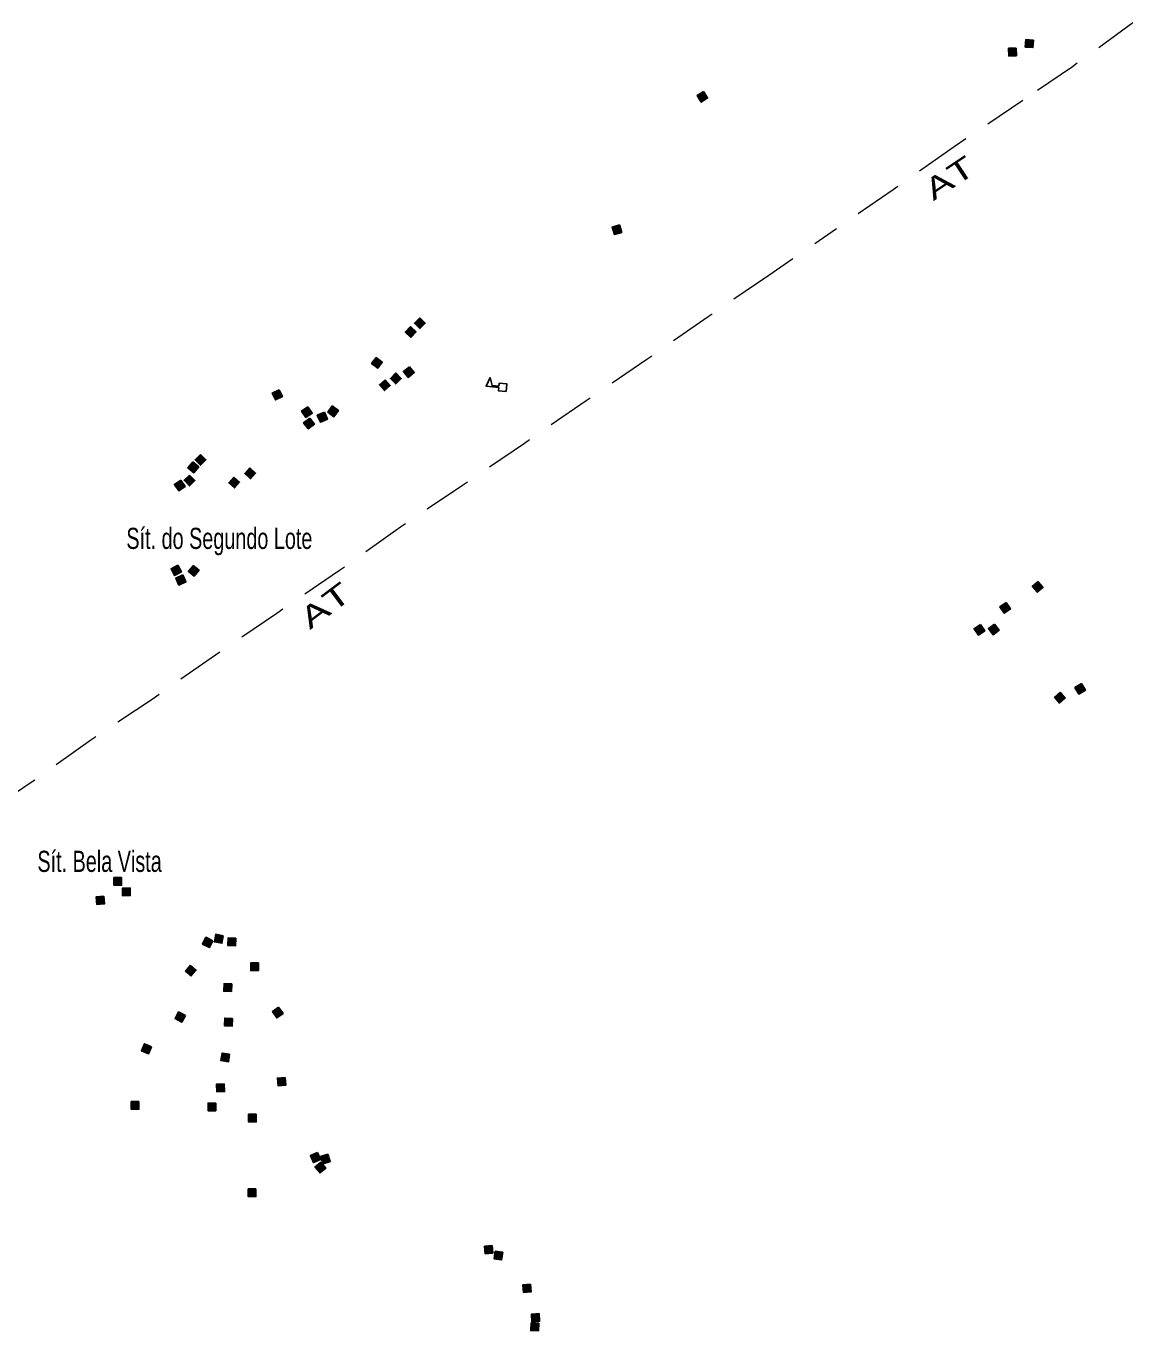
# Model space of a CAD drawing. Extents: x 679 to 705, y 7427.4 to 7455.4.
# Drawn here: x 687.983 to 692.169, y 7435.063 to 7439.999 of the extents above; entities that cross this region are included whole.
import ezdxf
from ezdxf.enums import TextEntityAlignment as Align

# ---------------------------------------------------------------- set-up
doc = ezdxf.new("R2010")
doc.units = 0
doc.header["$LTSCALE"] = 0.032
doc.linetypes.add('DOT_DASHED', pattern=[7.7, 5, -1.2, 0.3, -1.2])
for name, color, linetype, lineweight in [('2', 7, 'Continuous', 25), ('4', 7, 'Continuous', 25), ('56', 7, 'DOT_DASHED', 13)]:
    doc.layers.add(name, color=color, linetype=linetype, lineweight=lineweight)
doc.layers.add('61', color=7, linetype='Continuous')

msp = doc.modelspace()

# ---------------------------------------------------------------- hatches: boundary and pattern name
at = {"layer": '2'}
for points in [[(691.7282, 7439.9161), (691.7291, 7439.8871), (691.7001, 7439.8863), (691.6993, 7439.9152)], [(691.7935, 7439.9465), (691.7912, 7439.9176), (691.7623, 7439.9199), (691.7646, 7439.9488)], [(690.5453, 7439.7517), (690.5609, 7439.7272), (690.5365, 7439.7116), (690.5209, 7439.7361)], [(690.2281, 7439.2468), (690.2361, 7439.2189), (690.2082, 7439.2109), (690.2002, 7439.2387)], [(689.4724, 7438.8958), (689.4931, 7438.8755), (689.4728, 7438.8548), (689.4521, 7438.8751)], [(689.4369, 7438.8623), (689.458, 7438.8425), (689.4382, 7438.8213), (689.417, 7438.8412)], [(689.3071, 7438.7456), (689.3304, 7438.7283), (689.3131, 7438.705), (689.2898, 7438.7223)], [(689.3819, 7438.6868), (689.4022, 7438.6661), (689.3815, 7438.6458), (689.3612, 7438.6665)], [(689.4332, 7438.7107), (689.4514, 7438.6881), (689.4288, 7438.6699), (689.4106, 7438.6925)], [(689.3417, 7438.6613), (689.3606, 7438.6393), (689.3386, 7438.6204), (689.3197, 7438.6423)], [(688.9398, 7438.6237), (688.9528, 7438.5978), (688.9268, 7438.5848), (688.9139, 7438.6107)], [(689.049, 7438.5589), (689.0652, 7438.5348), (689.0411, 7438.5186), (689.0249, 7438.5427)], [(689.1113, 7438.5388), (689.123, 7438.5123), (689.0965, 7438.5006), (689.0847, 7438.5271)], [(689.1413, 7438.5621), (689.1646, 7438.5449), (689.1473, 7438.5216), (689.124, 7438.5388)], [(689.056, 7438.516), (689.0734, 7438.4928), (689.0502, 7438.4754), (689.0328, 7438.4986)], [(688.6138, 7438.3502), (688.6361, 7438.3317), (688.6175, 7438.3094), (688.5952, 7438.328)], [(688.6427, 7438.3791), (688.6631, 7438.3585), (688.6426, 7438.338), (688.6221, 7438.3586)], [(688.6016, 7438.3009), (688.6217, 7438.2799), (688.6007, 7438.2599), (688.5807, 7438.2809)], [(688.7688, 7438.2928), (688.7907, 7438.2739), (688.7718, 7438.2519), (688.7498, 7438.2709)], [(688.8299, 7438.328), (688.8513, 7438.3084), (688.8317, 7438.287), (688.8103, 7438.3066)], [(688.5682, 7438.2814), (688.5844, 7438.2574), (688.5604, 7438.2412), (688.5442, 7438.2652)], [(688.5572, 7437.9597), (688.5705, 7437.934), (688.5447, 7437.9207), (688.5314, 7437.9464)], [(688.6149, 7437.9589), (688.6372, 7437.9404), (688.6187, 7437.918), (688.5964, 7437.9365)], [(688.5757, 7437.9227), (688.5877, 7437.8963), (688.5612, 7437.8843), (688.5493, 7437.9107)], [(691.8109, 7437.8983), (691.8295, 7437.876), (691.8072, 7437.8575), (691.7887, 7437.8797)], [(691.6898, 7437.8183), (691.7064, 7437.7946), (691.6827, 7437.7779), (691.666, 7437.8017)], [(691.593, 7437.7353), (691.609, 7437.7112), (691.5849, 7437.6951), (691.5688, 7437.7192)], [(691.646, 7437.7371), (691.6635, 7437.7139), (691.6404, 7437.6964), (691.6229, 7437.7196)], [(691.9749, 7437.5117), (691.9898, 7437.4869), (691.965, 7437.472), (691.9501, 7437.4968)], [(691.8949, 7437.479), (691.9138, 7437.457), (691.8917, 7437.4381), (691.8729, 7437.4601)], [(688.3444, 7436.7778), (688.3444, 7436.7488), (688.3154, 7436.7488), (688.3154, 7436.7778)], [(688.277, 7436.7073), (688.2797, 7436.6784), (688.2508, 7436.6757), (688.2481, 7436.7046)], [(688.3762, 7436.7389), (688.3773, 7436.7099), (688.3483, 7436.7088), (688.3472, 7436.7378)], [(688.7291, 7436.558), (688.7239, 7436.5295), (688.6953, 7436.5348), (688.7006, 7436.5633)], [(688.6895, 7436.5391), (688.6765, 7436.5132), (688.6506, 7436.5261), (688.6635, 7436.5521)], [(688.7769, 7436.5486), (688.775, 7436.5196), (688.7461, 7436.5214), (688.7479, 7436.5504)], [(688.6047, 7436.4466), (688.6268, 7436.4278), (688.608, 7436.4057), (688.5859, 7436.4244)], [(688.8617, 7436.4552), (688.8617, 7436.4262), (688.8327, 7436.4262), (688.8327, 7436.4552)], [(688.7611, 7436.376), (688.76, 7436.347), (688.731, 7436.3481), (688.7321, 7436.3771)], [(688.5857, 7436.2559), (688.5718, 7436.2304), (688.5464, 7436.2443), (688.5602, 7436.2697)], [(688.9383, 7436.2876), (688.9551, 7436.264), (688.9315, 7436.2471), (688.9147, 7436.2707)], [(688.7637, 7436.2454), (688.763, 7436.2164), (688.734, 7436.2171), (688.7347, 7436.2461)], [(688.4578, 7436.1375), (688.4459, 7436.111), (688.4195, 7436.1229), (688.4314, 7436.1494)], [(688.7531, 7436.1097), (688.7488, 7436.0811), (688.7201, 7436.0854), (688.7244, 7436.114)], [(688.9627, 7436.0216), (688.9651, 7435.9926), (688.9362, 7435.9903), (688.9338, 7436.0192)], [(688.7323, 7435.9972), (688.7336, 7435.9682), (688.7046, 7435.9669), (688.7033, 7435.9959)], [(688.4097, 7435.9305), (688.4097, 7435.9015), (688.3807, 7435.9015), (688.3807, 7435.9305)], [(688.7006, 7435.9249), (688.7006, 7435.8959), (688.6716, 7435.8959), (688.6716, 7435.9249)], [(688.8538, 7435.8827), (688.8538, 7435.8537), (688.8248, 7435.8537), (688.8248, 7435.8827)], [(689.0851, 7435.7379), (689.0967, 7435.7113), (689.0701, 7435.6998), (689.0585, 7435.7264)], [(689.1246, 7435.7316), (689.1338, 7435.7041), (689.1063, 7435.6949), (689.0971, 7435.7225)], [(689.0984, 7435.7011), (689.1165, 7435.6785), (689.0939, 7435.6604), (689.0758, 7435.683)], [(688.8524, 7435.6001), (688.8524, 7435.5711), (688.8234, 7435.5711), (688.8234, 7435.6001)], [(689.7462, 7435.3862), (689.7488, 7435.3573), (689.72, 7435.3546), (689.7173, 7435.3835)], [(689.7858, 7435.3605), (689.7818, 7435.3318), (689.7531, 7435.3358), (689.7571, 7435.3645)], [(689.8914, 7435.2395), (689.8931, 7435.2106), (689.8641, 7435.2089), (689.8624, 7435.2378)], [(689.9238, 7435.1284), (689.9253, 7435.0994), (689.8963, 7435.0979), (689.8949, 7435.1269)], [(689.9223, 7435.092), (689.9211, 7435.063), (689.8921, 7435.0642), (689.8933, 7435.0932)]]:
    msp.add_hatch(color=256, dxfattribs=at).paths.add_polyline_path(points)

# ---------------------------------------------------------------- linework, layer by layer
for points in [[(691.7282, 7439.9161), (691.7291, 7439.8871), (691.7001, 7439.8863), (691.6993, 7439.9152)], [(691.7935, 7439.9465), (691.7912, 7439.9176), (691.7623, 7439.9199), (691.7646, 7439.9488)], [(690.5453, 7439.7517), (690.5609, 7439.7272), (690.5365, 7439.7116), (690.5209, 7439.7361)], [(690.2281, 7439.2468), (690.2361, 7439.2189), (690.2082, 7439.2109), (690.2002, 7439.2387)], [(689.4724, 7438.8958), (689.4931, 7438.8755), (689.4728, 7438.8548), (689.4521, 7438.8751)], [(689.4369, 7438.8623), (689.458, 7438.8425), (689.4382, 7438.8213), (689.417, 7438.8412)], [(689.3071, 7438.7456), (689.3304, 7438.7283), (689.3131, 7438.705), (689.2898, 7438.7223)], [(689.3819, 7438.6868), (689.4022, 7438.6661), (689.3815, 7438.6458), (689.3612, 7438.6665)], [(689.4332, 7438.7107), (689.4514, 7438.6881), (689.4288, 7438.6699), (689.4106, 7438.6925)], [(689.3417, 7438.6613), (689.3606, 7438.6393), (689.3386, 7438.6204), (689.3197, 7438.6423)], [(688.9398, 7438.6237), (688.9528, 7438.5978), (688.9268, 7438.5848), (688.9139, 7438.6107)], [(689.049, 7438.5589), (689.0652, 7438.5348), (689.0411, 7438.5186), (689.0249, 7438.5427)], [(689.1113, 7438.5388), (689.123, 7438.5123), (689.0965, 7438.5006), (689.0847, 7438.5271)], [(689.1413, 7438.5621), (689.1646, 7438.5449), (689.1473, 7438.5216), (689.124, 7438.5388)], [(689.056, 7438.516), (689.0734, 7438.4928), (689.0502, 7438.4754), (689.0328, 7438.4986)], [(688.6138, 7438.3502), (688.6361, 7438.3317), (688.6175, 7438.3094), (688.5952, 7438.328)], [(688.6427, 7438.3791), (688.6631, 7438.3585), (688.6426, 7438.338), (688.6221, 7438.3586)], [(688.6016, 7438.3009), (688.6217, 7438.2799), (688.6007, 7438.2599), (688.5807, 7438.2809)], [(688.7688, 7438.2928), (688.7907, 7438.2739), (688.7718, 7438.2519), (688.7498, 7438.2709)], [(688.8299, 7438.328), (688.8513, 7438.3084), (688.8317, 7438.287), (688.8103, 7438.3066)], [(688.5682, 7438.2814), (688.5844, 7438.2574), (688.5604, 7438.2412), (688.5442, 7438.2652)], [(688.5572, 7437.9597), (688.5705, 7437.934), (688.5447, 7437.9207), (688.5314, 7437.9464)], [(688.6149, 7437.9589), (688.6372, 7437.9404), (688.6187, 7437.918), (688.5964, 7437.9365)], [(688.5757, 7437.9227), (688.5877, 7437.8963), (688.5612, 7437.8843), (688.5493, 7437.9107)], [(691.8109, 7437.8983), (691.8295, 7437.876), (691.8072, 7437.8575), (691.7887, 7437.8797)], [(691.6898, 7437.8183), (691.7064, 7437.7946), (691.6827, 7437.7779), (691.666, 7437.8017)], [(691.593, 7437.7353), (691.609, 7437.7112), (691.5849, 7437.6951), (691.5688, 7437.7192)], [(691.646, 7437.7371), (691.6635, 7437.7139), (691.6404, 7437.6964), (691.6229, 7437.7196)], [(691.9749, 7437.5117), (691.9898, 7437.4869), (691.965, 7437.472), (691.9501, 7437.4968)], [(691.8949, 7437.479), (691.9138, 7437.457), (691.8917, 7437.4381), (691.8729, 7437.4601)], [(688.3444, 7436.7778), (688.3444, 7436.7488), (688.3154, 7436.7488), (688.3154, 7436.7778)], [(688.277, 7436.7073), (688.2797, 7436.6784), (688.2508, 7436.6757), (688.2481, 7436.7046)], [(688.3762, 7436.7389), (688.3773, 7436.7099), (688.3483, 7436.7088), (688.3472, 7436.7378)], [(688.7291, 7436.558), (688.7239, 7436.5295), (688.6953, 7436.5348), (688.7006, 7436.5633)], [(688.6895, 7436.5391), (688.6765, 7436.5132), (688.6506, 7436.5261), (688.6635, 7436.5521)], [(688.7769, 7436.5486), (688.775, 7436.5196), (688.7461, 7436.5214), (688.7479, 7436.5504)], [(688.6047, 7436.4466), (688.6268, 7436.4278), (688.608, 7436.4057), (688.5859, 7436.4244)], [(688.8617, 7436.4552), (688.8617, 7436.4262), (688.8327, 7436.4262), (688.8327, 7436.4552)], [(688.7611, 7436.376), (688.76, 7436.347), (688.731, 7436.3481), (688.7321, 7436.3771)], [(688.5857, 7436.2559), (688.5718, 7436.2304), (688.5464, 7436.2443), (688.5602, 7436.2697)], [(688.9383, 7436.2876), (688.9551, 7436.264), (688.9315, 7436.2471), (688.9147, 7436.2707)], [(688.7637, 7436.2454), (688.763, 7436.2164), (688.734, 7436.2171), (688.7347, 7436.2461)], [(688.4578, 7436.1375), (688.4459, 7436.111), (688.4195, 7436.1229), (688.4314, 7436.1494)], [(688.7531, 7436.1097), (688.7488, 7436.0811), (688.7201, 7436.0854), (688.7244, 7436.114)], [(688.9627, 7436.0216), (688.9651, 7435.9926), (688.9362, 7435.9903), (688.9338, 7436.0192)], [(688.7323, 7435.9972), (688.7336, 7435.9682), (688.7046, 7435.9669), (688.7033, 7435.9959)], [(688.4097, 7435.9305), (688.4097, 7435.9015), (688.3807, 7435.9015), (688.3807, 7435.9305)], [(688.7006, 7435.9249), (688.7006, 7435.8959), (688.6716, 7435.8959), (688.6716, 7435.9249)], [(688.8538, 7435.8827), (688.8538, 7435.8537), (688.8248, 7435.8537), (688.8248, 7435.8827)], [(689.0851, 7435.7379), (689.0967, 7435.7113), (689.0701, 7435.6998), (689.0585, 7435.7264)], [(689.1246, 7435.7316), (689.1338, 7435.7041), (689.1063, 7435.6949), (689.0971, 7435.7225)], [(689.0984, 7435.7011), (689.1165, 7435.6785), (689.0939, 7435.6604), (689.0758, 7435.683)], [(688.8524, 7435.6001), (688.8524, 7435.5711), (688.8234, 7435.5711), (688.8234, 7435.6001)], [(689.7462, 7435.3862), (689.7488, 7435.3573), (689.72, 7435.3546), (689.7173, 7435.3835)], [(689.7858, 7435.3605), (689.7818, 7435.3318), (689.7531, 7435.3358), (689.7571, 7435.3645)], [(689.8914, 7435.2395), (689.8931, 7435.2106), (689.8641, 7435.2089), (689.8624, 7435.2378)], [(689.9238, 7435.1284), (689.9253, 7435.0994), (689.8963, 7435.0979), (689.8949, 7435.1269)], [(689.9223, 7435.092), (689.9211, 7435.063), (689.8921, 7435.0642), (689.8933, 7435.0932)]]:
    msp.add_lwpolyline(points, close=True, dxfattribs=at)
at = {"layer": '4'}
for points in [[(689.771, 7438.6318), (689.7229, 7438.6366), (689.7378, 7438.6692), (689.7455, 7438.6393), (689.7715, 7438.6367)], [(689.7715, 7438.6367), (689.7727, 7438.6487), (689.8016, 7438.6458), (689.7987, 7438.617), (689.7698, 7438.6198), (689.771, 7438.6318)]]:
    msp.add_lwpolyline(points, dxfattribs=at)
at = {"layer": '56'}
msp.add_lwpolyline([(692.1694, 7440.0116), (691.9405, 7439.8452), (691.7528, 7439.7182), (691.4933, 7439.5421), (691.2622, 7439.3799), (690.7925, 7439.0559), (690.5628, 7438.8998), (690.3316, 7438.7379), (690.1013, 7438.5812), (689.868, 7438.4207), (689.6337, 7438.2607), (689.3988, 7438.1036), (689.1691, 7437.94), (688.9312, 7437.7773), (688.7, 7437.6197), (688.4634, 7437.4545), (688.2278, 7437.2978), (687.995, 7437.1322), (687.7505, 7436.9673)], dxfattribs=at)

# ---------------------------------------------------------------- texts
at = {"layer": '61'}
for rotation, width, p in [(33.592, 1.45, (691.4976, 7439.3914)), (36.785, 1.5, (689.1386, 7437.7752))]:
    msp.add_text('AT', height=0.08, rotation=rotation, dxfattribs=dict(at, width=width)).set_placement(p, align=Align.CENTER)
at = {"layer": '61', "width": 0.7}
for s, p in [('Sít. do Segundo Lote', (688.3624, 7438.0212)), ('Sít. Bela Vista', (688.0259, 7436.7994))]:
    msp.add_text(s, height=0.08, dxfattribs=at).set_placement(p)

doc.saveas('drawing.dxf')
